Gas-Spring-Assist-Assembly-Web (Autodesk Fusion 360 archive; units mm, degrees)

design "Gas-Spring-Assist-Assembly-Web" references "Air-Spring-Spindle-Right", "Air-Spring-Spindle-Left", "Air-Spring-Base-V2", "Air-Spring-Spindle-Top-and-Bottom"
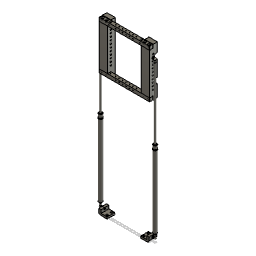
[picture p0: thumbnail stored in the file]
component_insert "Component Insert1"
ground "Ground1"
component_insert "Component Insert2"
component_insert "Component Insert3"
joint "Assemble1" alignAngle 0 alignOffsetX 0 alignOffsetY 0 alignOffsetZ 0
joint "Assemble2" alignAngle 0 alignOffsetX 0 alignOffsetY 0 alignOffsetZ 0
component_insert "Component Insert4"
joint "Assemble3" alignAngle 0 alignOffsetX 0 alignOffsetY 0 alignOffsetZ 0
base_feature "Base Feature"
joint "Assemble4" alignAngle 180 alignOffsetX 0 alignOffsetY 0 alignOffsetZ 0
copy_paste "CopyPaste1"
joint "Assemble5" alignAngle 0 alignOffsetX 0 alignOffsetY 0 alignOffsetZ 0
component_insert "Component Insert6"
joint "Assemble6" alignAngle 0 alignOffsetX 0 alignOffsetY 0 alignOffsetZ 0
component_insert "Component Insert7"
joint "Assemble7" alignAngle 0 alignOffsetX 0 alignOffsetY 0 alignOffsetZ 0
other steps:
create_component "CreateComponent1"
joint_origin "JointOrigin1"
joint_origin "JointOrigin2"
joint_origin "JointOrigin3"
joint_origin "JointOrigin4"

design "Air-Spring-Spindle-Right"
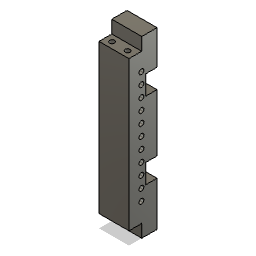
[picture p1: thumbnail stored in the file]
base_feature "Base Feature"
sketch "Sketch1" plane through (194.5, 0, 0) normal (1, 0, 0) x axis (0, 0, -1)
  line L1 (0, 240) -> (0, 0)
  line L2 (-45, 240) -> (0, 240)
  line L3 (-45, 0) -> (-45, 240)
  line L4 (0, 0) -> (-45, 0)
  line L5 (0, 240) -> (0, 0)
  line L6 (-9.33, 194) -> (-9.33, 184)
  line L7 (-9.33, 174) -> (-9.33, 184)
  line L8 (-9, 51) -> (-9, 61)
  line L9 (-9, 61) -> (-9, 71)
  line L10 (0, 71) -> (-9, 71)
  line L11 (0, 51) -> (-9, 51)
  line L12 (0, 194) -> (-9.33, 194)
  line L13 (0, 174) -> (-9.33, 174)
  line L14 (-24.5, 0.5) -> (-24.5, -20)
  line L15 (-45, 0.5) -> (-24.5, 0.5)
  line L16 (-45, 239.5) -> (-45, 0.5)
  line L17 (-24.5, 239.5) -> (-45, 239.5)
  line L18 (-24.5, 260) -> (-24.5, 239.5)
  line L19 (0, 260) -> (-24.5, 260)
  line L20 (0, -20) -> (0, 260)
  line L21 (-24.5, -20) -> (0, -20)
  line L22 (-45, 184) -> (-9.33, 184)
  line L23 (-45, 184) -> (-19.33, 184)
  line L24 (-25, 239.5) -> (-25, 184)
  line L25 (-25, 0) -> (-25, 184)
  line L26 (-18, 174) -> (0, 174)
  line L27 (-18, 205) -> (-18, 174)
  line L28 (0, 205) -> (-18, 205)
  line L29 (0, 174) -> (0, 205)
  line L30 (-18, 82) -> (0, 82)
  line L31 (-18, 51) -> (-18, 82)
  line L32 (0, 51) -> (-18, 51)
  line L33 (0, 82) -> (0, 51)
  line L34 (0, 0) -> (-45, 0)
  circle C1 centre (-9.33, 184) radius 4
  circle C2 centre (-9, 61) radius 4
  circle C3 centre (-9.33, 184) radius 4
  circle C4 centre (-9, 61) radius 4
  circle C5 centre (-9.33, 184) radius 10
  circle C6 centre (-9, 61) radius 10
  circle C7 centre (-25, 229.5) radius 4
  circle C8 centre (-25, 211.5) radius 4
  circle C9 centre (-25, 193.5) radius 4
  circle C10 centre (-25, 175.5) radius 4
  circle C11 centre (-25, 157.5) radius 4
  circle C12 centre (-25, 139.5) radius 4
  circle C13 centre (-25, 121.5) radius 4
  circle C14 centre (-25, 103.5) radius 4
  circle C15 centre (-25, 85.5) radius 4
  circle C16 centre (-25, 67.5) radius 4
  circle C17 centre (-25, 49.5) radius 4
  circle C18 centre (-25, 31.5) radius 4
  circle C19 centre (-25, 13.5) radius 4
  circle C20 centre (48.9891, 204) radius 4
  circle C21 centre (50.9273, 81) radius 4
  point P8 (-9.33, 184)
  point P14 (-9.33, 184)
  point P15 (-9.33, 194)
  point P16 (-9.33, 184)
  point P17 (-9.33, 174)
  point P9 (-9, 61)
  point P18 (-9, 61)
  point P19 (-9, 51)
  point P20 (-9, 71)
  point P21 (-9, 61)
  point P22 (0, 71)
  point P23 (0, 51)
  point P24 (0, 194)
  point P25 (0, 174)
  point P10 (-9.33, 184)
  point P35 (-9.33, 184)
  point P36 (-45, 184)
  point P37 (-19.33, 184)
  point P39 (-25, 239.5)
  point P40 (-25, 0)
  point P34 (-25, 229.5)
  point P58 (0, 82)
  point P61 (0, 51)
  point P53 (48.9891, 204)
  point P54 (50.9273, 81)
  concentric C1 C5
  concentric C4 C6
  coincident P8 P14
  coincident C5 P15
  parallel L5 L6
  coincident P8 P16
  coincident C5 P17
  parallel L6 L7
  coincident P9 P18
  coincident C6 P19
  parallel L5 L8
  coincident C6 P20
  coincident P9 P21
  parallel L8 L9
  coincident L5 P22
  tangent C6 L10
  coincident L5 P23
  tangent C6 L11
  coincident L5 P24
  tangent C5 L12
  coincident L5 P25
  perpendicular L5 L13
  coincident P10 P35
  coincident L16 P36
  perpendicular L3 L22
  coincident C5 P37
  coincident L22 P37
  coincident L17 P39
  perpendicular L17 L24
  coincident L4 P40
  perpendicular L4 L25
  coincident P34 L24
  horizontal L26
  vertical L27
  horizontal L28
  vertical L29
  horizontal L30
  vertical L31
  horizontal L32
  vertical L33
  coincident L5 P58
  coincident P23 P61
  dimension "d55" diameter C5 = 20
  dimension "d56" diameter C6 = 20
  dimension "d59" diameter C7 C13 = 8
  dimension "d60" distance P34 P39 = 10
  dimension "d93" distance L16 L24 = 20
  dimension "d216" diameter C20 = 8
  dimension "d217" diameter C21 = 8
  dimension "d218" distance P53 P54 = 123
  dimension "d219" distance L19 P53 = 56
  dimension "d220" distance L19 L28 = 55
  dimension "d221" distance L27 L29 = 18
  dimension "d222" distance L30 L34 = 82
  dimension "d223" distance L31 L33 = 18
  dimension "d63" R-Pattern1-uDistance = 0
  dimension "d64" R-Pattern1-vDistance = -18
extrude "Extrude1" new body sketch "Sketch1" profile of L1 L2 L3 L4 C5 C6 L5 L11 L13 L14 L15 L16 L17 L18 L19 L20 L21 C7 C8 C9 C10 C11 C12 C13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 along normal blind 49
extrude "Extrude3" cut of existing geometry blind -1
sketch "Sketch3" plane through (0, 239.5, 0) normal (0, 1, 0) x axis (-1, 0, 0)
  line L1 (-195.5, 45) -> (-195.5, 24.5)
  line L2 (-243.5, 45) -> (-195.5, 45)
  line L3 (-243.5, 24.5) -> (-243.5, 45)
  line L4 (-195.5, 24.5) -> (-243.5, 24.5)
  circle C1 centre (-231.5, 35) radius 5
  circle C2 centre (-206.5, 35) radius 5
  circle C3 centre (-231.5, 35) radius 4
  circle C4 centre (-206.5, 35) radius 4
  concentric C1 C3
  concentric C2 C4
  dimension "d250" diameter C3 = 8
  dimension "d251" diameter C4 = 8
extrude "Extrude4" cut sketch "Sketch3" profile of C3 C4 against normal blind 20
sketch "Sketch4" plane through (0, 0.5, 0) normal (0, -1, 0) x axis (1, 0, 0)
  line L1 (195.5, 24.5) -> (195.5, 45)
  line L2 (243.5, 24.5) -> (195.5, 24.5)
  line L3 (243.5, 45) -> (243.5, 24.5)
  line L4 (195.5, 45) -> (243.5, 45)
  circle C1 centre (206.5, 35) radius 4
  circle C2 centre (231.5, 35) radius 4
extrude "Extrude5" cut sketch "Sketch4" profile of C1 C2 against normal blind 20

design "Air-Spring-Spindle-Top-and-Bottom"
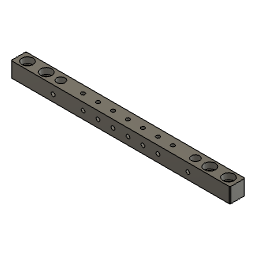
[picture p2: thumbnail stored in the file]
base_feature "Base Feature"
sketch "Sketch7" plane through (0, 260, 0) normal (0, 1, 0) x axis (-1, 0, 0)
  line L1 (49, 45) -> (49, 25)
  line L2 (-243.5, 45) -> (49, 45)
  line L3 (-243.5, 25) -> (-243.5, 45)
  line L4 (49, 25) -> (-243.5, 25)
  circle C1 centre (-187.15, 34.81) radius 2.5
  circle C2 centre (-7.25, 34.64) radius 2.5
sketch "Sketch1" plane through (0, 240, 0) normal (0, 1, 0) x axis (-1, 0, 0)
  line L1 (-167.1, 23) -> (-167.1, 0)
  line L2 (-27.4, 23) -> (-167.1, 23)
  line L3 (-27.4, 0) -> (-27.4, 23)
  line L4 (0, 0) -> (-27.4, 0)
  line L5 (0, 45) -> (0, 0)
  line L6 (-194.5, 45) -> (0, 45)
  line L7 (-194.5, 0) -> (-194.5, 45)
  line L8 (-167.1, 0) -> (-194.5, 0)
  line L9 (0, 45) -> (-194.5, 45)
  line L10 (-194.5, 45) -> (-194.5, 0)
  line L11 (0, 45) -> (0, 0)
  line L12 (-243.5, 45) -> (49, 45)
  line L13 (-243.5, 25) -> (-243.5, 45)
  line L14 (49, 25) -> (-243.5, 25)
  line L15 (49, 45) -> (49, 25)
  circle C1 centre (-7.25, 34.64) radius 2.5
  circle C2 centre (-187.15, 34.81) radius 2.5
  circle C3 centre (-7.25, 34.64) radius 2.5
  circle C4 centre (-7.25, 34.64) radius 2.5
  circle C5 centre (-187.15, 34.81) radius 2.5
  circle C6 centre (-187.15, 34.81) radius 2.5
  horizontal L12
  vertical L13
  horizontal L14
  vertical L15
  collinear L9 L12
  dimension "d44" distance L5 L15 = 49
  dimension "d45" distance L10 L13 = 49
  dimension "d46" distance L12 L14 = 20
extrude "Extrude1" new body sketch "Sketch1" profile of C1 C2 L5 L6 L7 C3 C4 C5 C6 L9 L10 L11 L12 L13 L14 L15 along normal blind 20
sketch "Sketch2" plane through (0, 260, 0) normal (0, 1, 0) x axis (-1, 0, 0)
hole "Hole1" HoleDepth 20 HoleDiameter 10 TipAngle 180 CBDepth 8 CBDiameter 15
sketch "Sketch3" plane through (0, 260, 0) normal (0, 1, 0) x axis (-1, 0, 0)
  line L1 (49, 45) -> (49, 25)
  line L2 (-243.5, 45) -> (49, 45)
  line L3 (-243.5, 25) -> (-243.5, 45)
  line L4 (49, 25) -> (-243.5, 25)
  circle C1 centre (-206.5, 35) radius 7.5
  circle C2 centre (37, 35) radius 7.5
  circle C3 centre (12, 35) radius 7.5
  circle C4 centre (-231.5, 35) radius 7.5
  circle C5 centre (-187.15, 34.81) radius 2.5
  circle C6 centre (-7.25, 34.64) radius 2.5
  circle C7 centre (-7.25, 34.64) radius 2.5
  circle C8 centre (-187.15, 34.81) radius 2.5
  circle C9 centre (-7.25, 34.64) radius 5.5
  circle C10 centre (-187.15, 34.81) radius 5.5
  concentric C7 C9
  concentric C5 C10
  dimension "d94" diameter C9 = 11
  dimension "d95" diameter C10 = 11
extrude "Extrude2" cut sketch "Sketch3" profile of C5 C6 C7 C8 C9 C10 against normal blind 8
sketch "Sketch4" plane through (0, 0, 45) normal (0, 0, 1) x axis (1, 0, 0)
  line L1 (243.5, 240) -> (-49, 240)
  line L2 (243.5, 260) -> (243.5, 240)
  line L3 (-49, 260) -> (243.5, 260)
  line L4 (-49, 240) -> (-49, 260)
  line L5 (4.75, 252) -> (9.75, 252)
  line L6 (9.75, 240) -> (4.75, 240)
  line L7 (184.65, 252) -> (189.65, 252)
  line L8 (189.65, 240) -> (184.65, 240)
  line L9 (4.75, 240) -> (4.75, 252)
  line L10 (9.75, 240) -> (9.75, 252)
  line L11 (184.65, 240) -> (184.65, 252)
  line L12 (189.65, 240) -> (189.65, 252)
  circle C1 centre (7.25, 249) radius 2.5
  circle C2 centre (187.15, 249) radius 2.5
  point P7 (4.75, 252)
  point P14 (4.75, 252)
  point P8 (4.75, 240)
  point P15 (4.75, 240)
  point P6 (9.75, 252)
  point P16 (9.75, 252)
  point P9 (9.75, 240)
  point P17 (9.75, 240)
  point P11 (184.65, 252)
  point P18 (184.65, 252)
  point P12 (184.65, 240)
  point P19 (184.65, 240)
  point P10 (189.65, 252)
  point P20 (189.65, 252)
  point P13 (189.65, 240)
  point P21 (189.65, 240)
  point P22 (7.25, 249)
  point P23 (187.15, 249)
  coincident P7 P14
  coincident P8 P15
  coincident P6 P16
  coincident P9 P17
  coincident P11 P18
  coincident P12 P19
  coincident P10 P20
  coincident P13 P21
  tangent L10 C1
  tangent L12 C2
  dimension "d122" diameter C1 = 5
  dimension "d123" diameter C2 = 5
  dimension "d124" distance L5 P22 = 3
  dimension "d125" distance L7 P23 = 3
extrude "Extrude3" cut sketch "Sketch4" profile of C1 C2 against normal blind 10
chamfer "Chamfer1" sketch "Sketch7" distance 1
sketch "Sketch5" plane through (0, 0, 45) normal (0, 0, 1) x axis (1, 0, 0)
  line L1 (-48, 240) -> (-48, 260)
  line L2 (242.5, 240) -> (-48, 240)
  line L3 (242.5, 260) -> (242.5, 240)
  line L4 (-48, 260) -> (242.5, 260)
  line L5 (97.25, 240) -> (97.25, 260)
  line L6 (-48, 250) -> (242.5, 250)
  circle C1 centre (187.15, 249) radius 2.5
  circle C2 centre (7.25, 249) radius 2.5
  circle C3 centre (87.25, 250) radius 2.5
  circle C4 centre (107.25, 250) radius 2.5
  circle C5 centre (67.25, 250) radius 2.5
  circle C6 centre (127.25, 250) radius 2.5
  circle C7 centre (47.25, 250) radius 2.5
  circle C8 centre (147.25, 250) radius 2.5
  point P8 (97.25, 260)
  point P9 (97.25, 240)
  point P10 (242.5, 250)
  point P11 (-48, 250)
  point P12 (87.25, 250)
  point P13 (107.25, 250)
  point P14 (67.25, 250)
  point P15 (127.25, 250)
  point P16 (47.25, 250)
  point P17 (147.25, 250)
  midpoint L4 P8
  midpoint L2 P9
  midpoint L3 P10
  midpoint L1 P11
  coincident L6 P12
  coincident L6 P13
  coincident L6 P14
  coincident L6 P15
  coincident L6 P16
  coincident L6 P17
  dimension "d187" diameter C3 = 5
  dimension "d188" diameter C4 = 5
  dimension "d189" diameter C5 = 5
  dimension "d190" diameter C6 = 5
  dimension "d191" distance L5 P13 = 10
  dimension "d192" distance L5 P12 = 10
  dimension "d193" distance P12 P14 = 20
  dimension "d194" distance P13 P15 = 20
  dimension "d195" diameter C7 = 5
  dimension "d196" diameter C8 = 5
  dimension "d197" distance P15 P17 = 20
  dimension "d198" distance P14 P16 = 20
extrude "Extrude4" cut sketch "Sketch5" profile of C3 C4 C5 C6 C7 C8 against normal blind 60
sketch "Sketch6" plane through (0, 260, 0) normal (0, 1, 0) x axis (-1, 0, 0)
  line L1 (49, 26) -> (48, 25)
  line L2 (49, 44) -> (49, 26)
  line L3 (48, 45) -> (49, 44)
  line L4 (-242.5, 45) -> (48, 45)
  line L5 (-243.5, 44) -> (-242.5, 45)
  line L6 (-243.5, 26) -> (-243.5, 44)
  line L7 (-242.5, 25) -> (-243.5, 26)
  line L8 (48, 25) -> (-242.5, 25)
  line L9 (-97.25, 45) -> (-97.25, 25)
  line L10 (-243.5, 35) -> (49, 35)
  circle C1 centre (-7.25, 34.64) radius 5.5
  circle C2 centre (-187.15, 34.81) radius 5.5
  circle C3 centre (-206.5, 35) radius 7.5
  circle C4 centre (37, 35) radius 7.5
  circle C5 centre (12, 35) radius 7.5
  circle C6 centre (-231.5, 35) radius 7.5
  circle C7 centre (-97.25, 35) radius 2.5
  circle C8 centre (-117.25, 35) radius 2.5
  circle C9 centre (-77.25, 35) radius 2.5
  circle C10 centre (-57.25, 35) radius 2.5
  circle C11 centre (-137.25, 35) radius 2.5
  circle C12 centre (-37.25, 35) radius 2.5
  circle C13 centre (-157.25, 35) radius 2.5
  point P16 (-97.25, 25)
  point P17 (-97.25, 45)
  point P18 (49, 35)
  point P19 (-243.5, 35)
  point P20 (-97.25, 35)
  point P21 (-117.25, 35)
  point P22 (-77.25, 35)
  point P23 (-57.25, 35)
  point P24 (-137.25, 35)
  point P25 (-37.25, 35)
  point P26 (-157.25, 35)
  midpoint L8 P16
  midpoint L4 P17
  midpoint L2 P18
  midpoint L6 P19
  coincident L10 P20
  coincident L9 P20
  coincident L10 P21
  coincident L10 P22
  coincident L10 P23
  coincident L10 P24
  coincident L10 P25
  coincident L10 P26
  dimension "d201" diameter C7 = 5
  dimension "d202" diameter C8 = 5
  dimension "d203" diameter C9 = 5
  dimension "d204" diameter C10 = 5
  dimension "d205" diameter C11 = 5
  dimension "d206" distance P20 P21 = 20
  dimension "d207" distance P21 P24 = 20
  dimension "d208" distance P20 P22 = 20
  dimension "d209" distance P22 P23 = 20
  dimension "d210" diameter C12 = 5
  dimension "d211" diameter C13 = 5
  dimension "d212" distance P24 P26 = 20
  dimension "d213" distance P23 P25 = 20
extrude "Extrude5" cut sketch "Sketch6" profile of C7 C8 C9 C10 C11 C12 C13 against normal blind 50

design "Air-Spring-Spindle-Left"
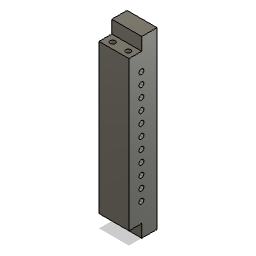
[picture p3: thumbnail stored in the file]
base_feature "Base Feature"
sketch "Sketch1" plane through (0, 0, 0) normal (-1, 0, 0) x axis (0, 0, 1)
  line L1 (0, 0) -> (0, 240)
  line L2 (45, 0) -> (0, 0)
  line L3 (45, 240) -> (45, 0)
  line L4 (0, 240) -> (45, 240)
  line L5 (45, 240) -> (25, 240)
  line L6 (45, 260) -> (45, 240)
  line L7 (25, 260) -> (45, 260)
  line L8 (25, 240) -> (25, 260)
  line L9 (25, 0) -> (45, 0)
  line L10 (25, -20) -> (25, 0)
  line L11 (45, -20) -> (25, -20)
  line L12 (45, 0) -> (45, -20)
  line L13 (0, 260) -> (25, 260)
  line L14 (0, 240) -> (0, 260)
  line L15 (25, 240) -> (0, 240)
  line L16 (25, 260) -> (25, 240)
  line L17 (25, 0) -> (0, 0)
  line L18 (25, -20) -> (25, 0)
  line L19 (0, -20) -> (25, -20)
  line L20 (0, 0) -> (0, -20)
  line L21 (24.5, 239.5) -> (24.5, 260)
  line L22 (45, 239.5) -> (24.5, 239.5)
  line L23 (24.5, 0.5) -> (24.5, -20)
  line L24 (45, 0.5) -> (24.5, 0.5)
  point P2 (0, 240)
  point P16 (0, 240)
  point P9 (25, 260)
  point P14 (25, 260)
  point P12 (25, -20)
  point P20 (25, -20)
  point P3 (0, 0)
  point P18 (0, 0)
  point P22 (24.5, 260)
  point P24 (45, 239.5)
  point P25 (24.5, -20)
  point P27 (45, 0.5)
  horizontal L13
  vertical L14
  horizontal L15
  vertical L16
  coincident P2 P16
  coincident P9 P14
  horizontal L17
  vertical L18
  horizontal L19
  vertical L20
  coincident P12 P20
  coincident P3 P18
  coincident L13 P22
  perpendicular L13 L21
  coincident L3 P24
  perpendicular L3 L22
  coincident L19 P25
  perpendicular L2 L23
  coincident L3 P27
  perpendicular L3 L24
  dimension "d51" distance L4 L22 = 0.5
  dimension "d52" distance L16 L21 = 0.5
  dimension "d53" distance L9 L24 = 0.5
  dimension "d54" distance L18 L23 = 0.5
extrude "Extrude1" new body sketch "Sketch1" profile of L1 L2 L3 L4 L13 L14 L15 L17 L19 L20 L21 L22 L23 L24 along normal blind 49
sketch "Sketch2" plane through (-49, 0, 0) normal (-1, 0, 0) x axis (0, 0, 1)
  line L1 (24.5, 0.5) -> (24.5, -20)
  line L2 (45, 0.5) -> (24.5, 0.5)
  line L3 (45, 239.5) -> (45, 0.5)
  line L4 (24.5, 239.5) -> (45, 239.5)
  line L5 (24.5, 260) -> (24.5, 239.5)
  line L6 (0, 260) -> (24.5, 260)
  line L7 (0, -20) -> (0, 260)
  line L8 (24.5, -20) -> (0, -20)
  circle C1 centre (25, 211.5) radius 4
  circle C2 centre (25, 211.5) radius 4
  circle C3 centre (25, 193.5) radius 4
  circle C4 centre (25, 193.5) radius 4
  circle C5 centre (25, 175.5) radius 4
  circle C6 centre (25, 175.5) radius 4
  circle C7 centre (25, 157.5) radius 4
  circle C8 centre (25, 157.5) radius 4
  circle C9 centre (25, 229.5) radius 4
  circle C10 centre (25, 211.5) radius 4
  circle C11 centre (25, 193.5) radius 4
  circle C12 centre (25, 175.5) radius 4
  circle C13 centre (25, 157.5) radius 4
  circle C14 centre (25, 139.5) radius 4
  circle C15 centre (25, 121.5) radius 4
  circle C16 centre (25, 103.5) radius 4
  circle C17 centre (25, 85.5) radius 4
  circle C18 centre (25, 67.5) radius 4
  circle C19 centre (25, 49.5) radius 4
  circle C20 centre (25, 31.5) radius 4
  circle C21 centre (25, 13.5) radius 4
extrude "Extrude2" cut sketch "Sketch2" profile of C1 C2 C3 C4 C5 C6 C7 C8 C10 C11 C12 C13 C14 C15 C16 C17 C18 C19 C20 against normal blind 49
sketch "Sketch3" plane through (0, 239.5, 0) normal (0, 1, 0) x axis (-1, 0, 0)
  line L1 (0, 24.5) -> (0, 45)
  line L2 (49, 24.5) -> (0, 24.5)
  line L3 (49, 45) -> (49, 24.5)
  line L4 (0, 45) -> (49, 45)
  circle C1 centre (37, 35) radius 5
  circle C2 centre (37, 35) radius 5
  circle C3 centre (12, 35) radius 5
  circle C4 centre (12, 35) radius 5
  circle C5 centre (37, 35) radius 4
  circle C6 centre (12, 35) radius 4
  concentric C1 C5
  concentric C3 C6
  dimension "d85" diameter C5 = 8
  dimension "d86" diameter C6 = 8
extrude "Extrude3" cut sketch "Sketch3" profile of C5 C6 against normal blind 20
sketch "Sketch4" plane through (0, 0.5, 0) normal (0, -1, 0) x axis (1, 0, 0)
  line L1 (0, 45) -> (0, 24.5)
  line L2 (-49, 45) -> (0, 45)
  line L3 (-49, 24.5) -> (-49, 45)
  line L4 (0, 24.5) -> (-49, 24.5)
  circle C1 centre (-37, 35) radius 5
  circle C2 centre (-12, 35) radius 5
  circle C3 centre (-37, 35) radius 4
  circle C4 centre (-12, 35) radius 4
  concentric C1 C3
  concentric C2 C4
  dimension "d89" diameter C3 = 8
  dimension "d90" diameter C4 = 8
extrude "Extrude4" cut sketch "Sketch4" profile of C3 C4 against normal blind 20
extrude "Extrude6" cut of existing geometry blind -1

design "Air-Spring-Base-V2"
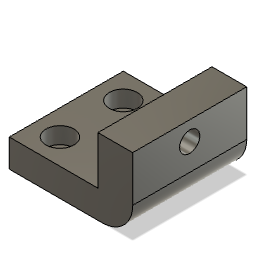
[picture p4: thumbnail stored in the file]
base_feature "Base Feature"
work_plane "WorkPlane1" AlongDistance 130
sketch "Sketch1" plane through (-25, -150, 12.25) normal (0, -1, 0) x axis (1, 0, 0)
  line L1 (-24, 32.75) -> (-24, 12.25)
  line L2 (-24, 12.25) -> (-24, 32.75)
  line L3 (-24, -12.25) -> (-24, 12.25)
  line L4 (-24, 12.25) -> (-24, -12.25)
  line L5 (-10.3, -12.25) -> (-24, -12.25)
  line L6 (-10.3, 32.75) -> (-10.3, -12.25)
  line L7 (-24, 32.75) -> (-10.3, 32.75)
  line L8 (-24, -12.25) -> (-24, 32.75)
  line L9 (-59, -12.25) -> (-24, -12.25)
  line L10 (-59, 32.75) -> (-59, -12.25)
  line L11 (-24, 32.75) -> (-59, 32.75)
  line L12 (-24, -12.25) -> (-24, 32.75)
  line L13 (-24, 16.75) -> (-24, 8.75)
  line L14 (-24, 16.75) -> (-24, 8.75)
  line L15 (-24, 16.75) -> (-24, 8.75)
  line L16 (-24, 16.75) -> (-24, 8.75)
  line L17 (-24, 16.75) -> (-24, 8.75)
  line L18 (-24, 16.75) -> (-24, 8.75)
  line L19 (-24, 16.75) -> (-24, 8.75)
  line L20 (-24, 16.75) -> (-24, 8.75)
  line L21 (-24, 16.75) -> (-24, 8.75)
  line L22 (-24, 16.75) -> (-24, 8.75)
  line L23 (-24, 16.75) -> (-24, 8.75)
  circle C1 centre (-49, -2.25) radius 3.25
  circle C2 centre (-49, 22.75) radius 3.25
  circle C3 centre (-49, -2.25) radius 5.5
  circle C4 centre (-49, 22.75) radius 5.5
  point P4 (-24, -12.25)
  point P5 (-24, -12.25)
  point P3 (-24, 32.75)
  point P8 (-24, 32.75)
  point P9 (-24, -12.25)
  point P14 (-49, 22.75)
  point P13 (-49, -2.25)
  horizontal L5
  vertical L6
  horizontal L7
  vertical L8
  coincident P4 P5
  coincident P3 P8
  horizontal L9
  vertical L10
  horizontal L11
  vertical L12
  coincident P4 P9
  collinear L7 L11
  concentric C1 C3
  concentric C2 C4
  dimension "d130" distance L6 L8 = 13.7 (= "8.7 mm + 5 mm")
  dimension "d131" distance L8 L10 = 35
  dimension "d132" diameter C1 = 6.5
  dimension "d133" diameter C2 = 6.5
  dimension "d134" distance L11 P14 = 10
  dimension "d135" distance L9 P13 = 10
  dimension "d136" distance L10 P13 = 10
  dimension "d137" distance L10 P14 = 10
  dimension "d138" diameter C3 = 11
  dimension "d139" diameter C4 = 11
extrude "Extrude1" new body sketch "Sketch1" profile of L1 L2 L3 L4 L5 L6 L7 L8 L9 L10 L11 L12 C1 C2 along normal blind 11
extrude "Extrude2" add sketch "Sketch1" profile of L1 L2 L3 L4 L5 L6 L7 L8 L12 against normal blind 19
fillet "Fillet1" radius 12
extrude "Extrude3" cut sketch "Sketch1" profile of C1 C2 C3 C4 along normal blind 6.5
sketch "Sketch2" plane through (-49, 0, 0) normal (-1, 0, 0) x axis (0, 0, 1)
  line L1 (45, -150) -> (0, -150)
  line L2 (45, -131) -> (45, -150)
  line L3 (0, -131) -> (45, -131)
  line L4 (0, -150) -> (0, -131)
  line L5 (24.5, 0.5) -> (24.5, -20)
  line L6 (45, 0.5) -> (24.5, 0.5)
  line L7 (45, 239.5) -> (45, 0.5)
  line L8 (24.5, 239.5) -> (45, 239.5)
  line L9 (24.5, 260) -> (24.5, 239.5)
  line L10 (0, 260) -> (24.5, 260)
  line L11 (0, -20) -> (0, 260)
  line L12 (24.5, -20) -> (0, -20)
  line L13 (22.5, 282.7781) -> (22.5, -150)
  circle C1 centre (22.5, -138.5) radius 4
  circle C2 centre (22.5, -138.5) radius 7.5
  circle C3 centre (25, 67.5) radius 4
  circle C4 centre (25, 139.5) radius 4
  circle C5 centre (25, 211.5) radius 4
  circle C6 centre (25, 157.5) radius 4
  circle C7 centre (25, 85.5) radius 4
  circle C8 centre (25, 49.5) radius 4
  circle C9 centre (25, 121.5) radius 4
  circle C10 centre (25, 193.5) radius 4
  circle C11 centre (25, 175.5) radius 4
  circle C12 centre (25, 103.5) radius 4
  circle C13 centre (25, 31.5) radius 4
  point P16 (22.5, -150)
  point P7 (22.5, -138.5)
  point P6 (22.5, -138.5)
  concentric C1 C2
  coincident L1 P16
  perpendicular L12 L13
  coincident P7 L13
  dimension "d148" diameter C1 = 8
  dimension "d149" distance L3 P6 = 7.5
  dimension "d150" diameter C2 = 15
  dimension "d256" distance L2 P6 = 22.5 (= "( 45 / 2 ) * 1 mm")
extrude "Extrude4" cut sketch "Sketch2" profile of C1 against normal blind 30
